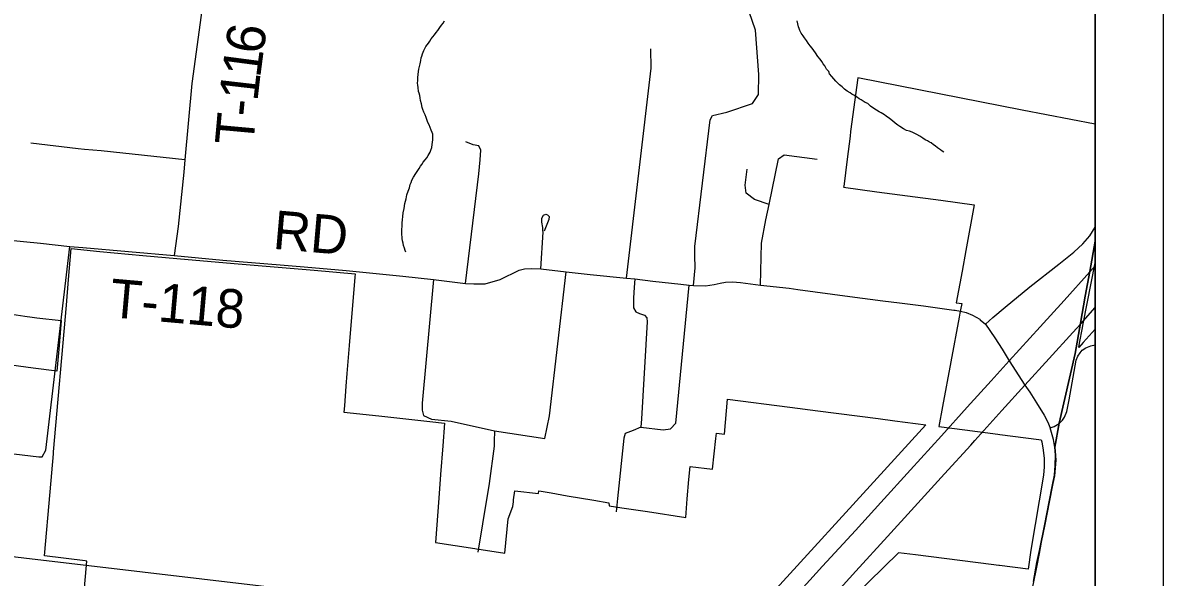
# Model space of a CAD drawing. Extents: x -7.3 to 34, y 0 to 22.
# Drawn here: x 7.321 to 9, y 18.898 to 19.714 of the extents above; entities that cross this region are included whole.
import ezdxf

# ---------------------------------------------------------------- set-up
doc = ezdxf.new("R2010")
doc.units = 0
for name, color, linetype in [('GM_X_Corporation', 7, 'Continuous'), ('GM_X_County_Road', 7, 'Continuous'), ('GM_X_Interstate_Route', 7, 'Continuous'), ('GM_X_Minor_River', 7, 'Continuous'), ('GM_X_Township_Road', 7, 'Continuous'), ('GM_X_Township_Road_Text', 7, 'Continuous'), ('SH_Data', 7, 'Continuous')]:
    doc.layers.add(name, color=color, linetype=linetype)

msp = doc.modelspace()

# ---------------------------------------------------------------- linework, layer by layer
at = {"layer": 'GM_X_Corporation'}
for points in [[(8.9, 14.1), (8.9, 19.7858), (8.8913, 19.7872), (7.8469, 19.8978), (7.6051, 19.9224), (6.9988, 19.9839), (6.9507, 19.9888), (6.4242, 20.0024), (6.4154, 20.0027), (6.0763, 20.0096), (6.0677, 20.0098), (6.0214, 20.0108), (5.9388, 20.0125), (5.8024, 20.0153), (4.9519, 20.0328), (4.9401, 20.0331), (4.9235, 20.0334), (4.7954, 20.036), (4.4762, 20.0428), (4.2328, 20.0479), (4.2288, 20.048), (2.7422, 20.0783)], [(8.8088, 18.8915), (8.8141, 18.9196), (8.8177, 18.9374), (8.8256, 18.9762), (8.8322, 19.0092), (8.8371, 19.0338), (8.8397, 19.0484), (8.841, 19.0624), (8.8412, 19.0775), (8.8403, 19.0896), (8.8467, 19.1247), (8.8704, 19.2273), (8.8782, 19.2717), (8.8852, 19.3116), (8.8919, 19.348), (8.9, 19.3924), (8.9, 19.7858)], [(8.9, 17.3436), (8.9, 19.2631), (8.8822, 19.2435), (8.8757, 19.2363), (8.8769, 19.2423), (8.8813, 19.2653), (8.8819, 19.2684), (8.8823, 19.2708), (8.8996, 19.3605), (8.9, 19.3625), (8.9, 19.5647), (8.7924, 19.5856), (8.5503, 19.6328), (8.5397, 19.5541), (8.5388, 19.5473), (8.5346, 19.5133), (8.5295, 19.4729), (8.5294, 19.4719), (8.5784, 19.4654), (8.6236, 19.4594), (8.6723, 19.4529), (8.7217, 19.4463), (8.7094, 19.3791), (8.7039, 19.3486), (8.6953, 19.3017), (8.6994, 19.3012), (8.7033, 19.3008), (8.7015, 19.2915), (8.7007, 19.2868), (8.6995, 19.2808), (8.6751, 19.1493), (8.6697, 19.12), (8.7078, 19.115), (8.7563, 19.1087), (8.7595, 19.1083), (8.8167, 19.1009), (8.8202, 19.1004), (8.8211, 19.0975), (8.8231, 19.085), (8.8245, 19.0727), (8.8247, 19.0604), (8.8236, 19.0481), (8.8053, 18.9378), (8.8012, 18.9097), (8.7588, 18.9151), (8.758, 18.9152), (8.7466, 18.9166), (8.6351, 18.9308), (8.6101, 18.934), (8.4786, 18.8052)], [(7.4105, 18.8711), (7.4151, 18.9217), (7.4122, 18.922), (7.3527, 18.9294), (7.3609, 19.0238), (7.3657, 19.0796), (7.366, 19.0825), (7.3848, 19.2985), (7.3881, 19.3362), (7.3917, 19.3816), (7.434, 19.3776), (7.4972, 19.3717), (7.5476, 19.367), (7.6316, 19.3598), (7.7495, 19.3497), (7.81, 19.3446), (7.8096, 19.3398), (7.8014, 19.2393), (7.798, 19.1979), (7.7965, 19.179), (7.7941, 19.1504), (7.7934, 19.141), (7.8447, 19.1354), (7.9024, 19.1291), (7.92, 19.1272), (7.9417, 19.1249), (7.9391, 19.0916), (7.9358, 19.0493), (7.9331, 19.0142), (7.9281, 18.949), (7.9864, 18.9401), (7.9911, 18.9394), (7.9958, 18.9387), (8.0305, 18.9334), (8.0355, 18.9841), (8.042, 19.0019), (8.043, 19.0089), (8.0433, 19.0117), (8.0451, 19.0253), (8.08, 19.0214), (8.0804, 19.0251), (8.0841, 19.0245), (8.0988, 19.022), (8.1223, 19.0179), (8.1615, 19.0112), (8.1835, 19.0077), (8.1842, 19.003), (8.1933, 19.0017), (8.2026, 19.0003), (8.2404, 18.9947), (8.2968, 18.9861), (8.2992, 19.0135), (8.3016, 19.0418), (8.3032, 19.0608), (8.3361, 19.057), (8.3414, 19.1021), (8.3418, 19.1059), (8.3423, 19.11), (8.3539, 19.1088), (8.3583, 19.1603), (8.4501, 19.1484), (8.4913, 19.1431), (8.5804, 19.1315), (8.6048, 19.1284), (8.6506, 19.1224), (8.3584, 18.8026)], [(8.9, 14.1), (8.9, 19.3924), (8.8919, 19.348), (8.8852, 19.3116), (8.8782, 19.2717), (8.8704, 19.2273), (8.8467, 19.1247), (8.8403, 19.0896), (8.8412, 19.0775), (8.841, 19.0624), (8.8397, 19.0484), (8.8371, 19.0338), (8.8322, 19.0092), (8.8256, 18.9762), (8.8177, 18.9374), (8.8141, 18.9196), (8.8088, 18.8915)], [(7.2979, 19.286), (7.3237, 19.2822), (7.3343, 19.2806), (7.3412, 19.2796), (7.3771, 19.2759), (7.3755, 19.2576), (7.3739, 19.2389), (7.3706, 19.2015), (7.336, 19.2059), (7.2812, 19.213)]]:
    msp.add_lwpolyline(points, dxfattribs=at)
msp.add_lwpolyline([(7.7589, 18.875), (7.6737, 17.8749), (6.6194, 17.9753), (6.71, 18.9987)], close=True, dxfattribs=at)
at = {"layer": 'GM_X_County_Road'}
msp.add_lwpolyline([(8.7923, 18.8076), (8.7989, 18.8415), (8.809, 18.8888), (8.8137, 18.9126), (8.8176, 18.9328), (8.8209, 18.9495), (8.8262, 18.9757), (8.8327, 19.0086), (8.8377, 19.0333), (8.8402, 19.0473), (8.8415, 19.0583), (8.8422, 19.0701), (8.8419, 19.077), (8.8406, 19.0891), (8.8386, 19.1005), (8.8337, 19.1181)], dxfattribs=at)
at = {"layer": 'GM_X_Interstate_Route'}
for points in [[(8.0485, 18.4186), (8.0571, 18.4281), (8.0916, 18.466), (8.1306, 18.5093), (8.1704, 18.5523), (8.2137, 18.6004), (8.2539, 18.6443), (8.2977, 18.6924), (8.3359, 18.735), (8.374, 18.7768), (8.4185, 18.8259), (8.4562, 18.8675), (8.4985, 18.9141), (8.5471, 18.967), (8.584, 19.0079), (8.6281, 19.0563), (8.6734, 19.1062), (8.7114, 19.1482), (8.7469, 19.1872), (8.7734, 19.2167), (8.8186, 19.2664), (8.8544, 19.3055), (8.8921, 19.3474), (8.9, 19.3561)], [(8.7165, 19.0926), (8.7226, 19.0992), (8.7623, 19.1433), (8.7964, 19.1809), (8.8321, 19.22), (8.8667, 19.2582), (8.8785, 19.2711), (8.9, 19.2949)], [(8.1035, 18.418), (8.1055, 18.4202), (8.1101, 18.4253), (8.1411, 18.4595), (8.181, 18.5035), (8.2198, 18.5461), (8.263, 18.5939), (8.3021, 18.6371), (8.3476, 18.6868), (8.3849, 18.728), (8.4244, 18.7711), (8.4683, 18.8193), (8.5057, 18.8606), (8.5476, 18.9069), (8.5941, 18.958), (8.6337, 19.0017), (8.678, 19.0504), (8.7165, 19.0926)]]:
    msp.add_lwpolyline(points, dxfattribs=at)
at = {"layer": 'GM_X_Minor_River'}
for points in [[(7.8845, 19.3764), (7.8838, 19.3791), (7.8827, 19.3825), (7.8813, 19.3863), (7.8806, 19.3898), (7.8799, 19.3932), (7.8792, 19.3963), (7.8793, 19.3989), (7.879, 19.402), (7.8787, 19.4058), (7.8788, 19.4099), (7.8793, 19.4149), (7.8794, 19.4194), (7.8798, 19.424), (7.8803, 19.4289), (7.8808, 19.4342), (7.8821, 19.4406), (7.8834, 19.4482), (7.8851, 19.455), (7.8863, 19.4607), (7.8883, 19.4664), (7.89, 19.4713), (7.8912, 19.4758), (7.8924, 19.4792), (7.8936, 19.4826), (7.896, 19.4867), (7.8992, 19.4923), (7.9023, 19.4968), (7.9042, 19.4998), (7.9062, 19.5028), (7.9082, 19.5054), (7.9101, 19.5088), (7.9129, 19.5122), (7.9156, 19.5152), (7.9176, 19.5185), (7.9191, 19.5212), (7.9203, 19.5238), (7.9215, 19.5264), (7.9227, 19.5306), (7.9236, 19.5347), (7.924, 19.5382), (7.9245, 19.5419), (7.9242, 19.5461), (7.9243, 19.5499), (7.9232, 19.5526), (7.9222, 19.5561), (7.9207, 19.5599), (7.9189, 19.5637), (7.9171, 19.5672), (7.916, 19.5702), (7.9146, 19.5745), (7.9132, 19.5787), (7.9114, 19.5825), (7.9099, 19.5863), (7.9088, 19.5894), (7.9075, 19.5947), (7.9064, 19.5997), (7.9057, 19.6035), (7.9051, 19.607), (7.9044, 19.6104), (7.9033, 19.6131), (7.9027, 19.6188), (7.9024, 19.6222), (7.902, 19.6253), (7.9021, 19.6291), (7.9022, 19.6332), (7.9027, 19.6385), (7.904, 19.6457), (7.9057, 19.6537), (7.9066, 19.6586), (7.9074, 19.6624), (7.9082, 19.665), (7.9091, 19.6684), (7.9111, 19.6733), (7.9142, 19.6793), (7.9181, 19.6842), (7.9201, 19.6868), (7.922, 19.6902), (7.9244, 19.6935), (7.9267, 19.6965), (7.9291, 19.6999), (7.9318, 19.7029), (7.9349, 19.707), (7.9373, 19.7104), (7.9396, 19.7137), (7.9416, 19.7171)], [(8.677, 19.5237), (8.6744, 19.5253), (8.6718, 19.5269), (8.6677, 19.53), (8.6643, 19.5328), (8.6617, 19.5343), (8.6583, 19.5371), (8.6557, 19.5383), (8.6527, 19.5402), (8.6497, 19.5418), (8.646, 19.5442), (8.6415, 19.5473), (8.637, 19.5497), (8.6332, 19.5517), (8.6302, 19.5529), (8.6265, 19.5545), (8.6219, 19.5557), (8.6178, 19.5581), (8.6122, 19.5612), (8.6092, 19.5632), (8.6055, 19.5663), (8.6014, 19.5695), (8.5969, 19.573), (8.592, 19.5765), (8.5894, 19.5785), (8.5846, 19.5816), (8.5819, 19.5828), (8.5778, 19.5852), (8.5737, 19.5879), (8.5688, 19.5911), (8.5648, 19.595), (8.561, 19.5969), (8.5584, 19.5985), (8.5554, 19.6005), (8.5524, 19.6021), (8.5498, 19.604), (8.5472, 19.6056), (8.5442, 19.6076), (8.5416, 19.6091), (8.5389, 19.6107), (8.5348, 19.6135), (8.5307, 19.6162), (8.527, 19.6197), (8.5233, 19.6228), (8.5207, 19.6252), (8.5181, 19.6283), (8.5151, 19.6314), (8.5121, 19.6348), (8.5088, 19.6391), (8.5074, 19.6422), (8.5044, 19.6457), (8.5015, 19.6507), (8.4993, 19.6537), (8.4975, 19.6572), (8.4949, 19.6603), (8.4915, 19.6642), (8.4879, 19.6699), (8.4831, 19.6765), (8.4801, 19.68), (8.4772, 19.6839), (8.4746, 19.6877), (8.472, 19.6919), (8.4698, 19.695), (8.4669, 19.6989), (8.4651, 19.7027), (8.464, 19.7054), (8.4629, 19.7081), (8.4619, 19.7123), (8.4608, 19.7169)]]:
    msp.add_lwpolyline(points, dxfattribs=at)
at = {"layer": 'GM_X_Township_Road'}
for p, q in [((8.7306, 19.2769), (8.7381, 19.2706)), ((8.1965, 19.0137), (8.1946, 18.9943)), ((7.9976, 18.9765), (7.9906, 18.9348))]:
    msp.add_line(p, q, dxfattribs=at)
for points in [[(7.6053, 19.9219), (7.5861, 19.7466), (7.5695, 19.6248), (7.5594, 19.5121), (7.5576, 19.494), (7.5493, 19.4144), (7.5434, 19.3715)], [(8.3085, 19.3272), (8.3108, 19.3535), (8.3105, 19.3714), (8.3105, 19.385), (8.3326, 19.571), (8.3362, 19.5774), (8.3575, 19.5826), (8.395, 19.5951), (8.404, 19.6085), (8.4044, 19.6378), (8.3994, 19.7032), (8.3902, 19.73), (8.3728, 19.7638), (8.3414, 19.8181)], [(8.2095, 19.3383), (8.246, 19.6474), (8.2455, 19.6755)], [(7.4112, 19.5277), (7.4023, 19.5285), (7.3323, 19.5368)], [(7.9727, 19.3305), (7.9923, 19.4919), (7.9942, 19.5121), (7.995, 19.5264), (7.9923, 19.5329), (7.9839, 19.5343), (7.973, 19.539)], [(7.5594, 19.5121), (7.4358, 19.5256), (7.4112, 19.5277)], [(8.4071, 19.3281), (8.4084, 19.3896), (8.4149, 19.424), (8.4196, 19.4468), (8.4333, 19.5137), (8.4418, 19.5199), (8.4902, 19.5131)], [(8.4196, 19.4468), (8.3981, 19.454), (8.3858, 19.4631), (8.3846, 19.4752), (8.3874, 19.4984)], [(8.0866, 19.4081), (8.0863, 19.4127), (8.0851, 19.4206), (8.0849, 19.4264), (8.0872, 19.4309), (8.0908, 19.4322), (8.0934, 19.4315), (8.0957, 19.4289), (8.0951, 19.4246), (8.0882, 19.4074)], [(8.0835, 19.352), (8.0868, 19.4058), (8.0866, 19.4081)], [(8.7381, 19.2706), (8.7493, 19.2805), (8.7672, 19.2956), (8.8038, 19.3254), (8.8461, 19.3587), (8.8682, 19.3766), (8.8815, 19.3889), (8.8918, 19.4007), (8.9, 19.413)], [(7.2031, 18.6729), (7.213, 18.7865), (7.2223, 18.8928), (7.2388, 18.9984), (7.2548, 19.0809), (7.258, 19.0854), (7.3442, 19.0751), (7.3492, 19.0753), (7.3547, 19.0851), (7.3897, 19.3848)], [(7.2968, 19.3946), (7.3465, 19.3896), (7.3897, 19.3848), (7.4089, 19.3832)], [(7.4089, 19.3832), (7.5434, 19.3715), (7.6151, 19.3647), (7.6994, 19.3576), (7.7349, 19.3549), (7.7966, 19.3495), (7.8801, 19.3413), (7.9256, 19.336), (7.9727, 19.3305), (7.9849, 19.3299), (8.0014, 19.3296), (8.0237, 19.3362), (8.0516, 19.3497), (8.0595, 19.352), (8.0696, 19.3522), (8.0835, 19.352), (8.121, 19.3477), (8.156, 19.3438), (8.2095, 19.3383), (8.2221, 19.337), (8.2482, 19.3337), (8.2897, 19.3294), (8.3021, 19.3277), (8.3085, 19.3272), (8.3258, 19.3267), (8.3389, 19.329), (8.3475, 19.3307), (8.3555, 19.3322), (8.3658, 19.3328), (8.3777, 19.332), (8.4071, 19.3281), (8.4491, 19.3232), (8.4617, 19.3213), (8.5383, 19.311), (8.5872, 19.3047), (8.6118, 19.3018), (8.6469, 19.2975), (8.6918, 19.2913), (8.6938, 19.2909)], [(8.0894, 19.1024), (8.096, 19.1354), (8.121, 19.3477)], [(7.9256, 19.336), (7.9088, 19.1543), (7.9086, 19.1437), (7.9109, 19.1361), (7.9223, 19.1306), (7.9516, 19.1277), (8.0154, 19.1136), (8.0894, 19.1024)], [(8.2221, 19.337), (8.221, 19.3245), (8.22, 19.3091), (8.22, 19.2945), (8.2235, 19.2885), (8.2287, 19.286), (8.2363, 19.2837), (8.2394, 19.2799), (8.2402, 19.2741), (8.2316, 19.1311), (8.2305, 19.1189), (8.2194, 19.1139), (8.2079, 19.1096), (8.2055, 19.1028), (8.1965, 19.0137)], [(8.2305, 19.1189), (8.2638, 19.1151), (8.2745, 19.1164), (8.2823, 19.125), (8.3021, 19.3277)], [(8.6938, 19.2909), (8.7017, 19.2896), (8.7098, 19.2874), (8.7193, 19.2835), (8.7298, 19.2776), (8.7306, 19.2769)], [(8.7381, 19.2706), (8.7519, 19.2505), (8.7628, 19.2338), (8.7734, 19.2167), (8.7964, 19.1809), (8.8037, 19.1702), (8.8135, 19.1547), (8.8245, 19.1365), (8.8294, 19.1274), (8.8337, 19.1181)], [(8.8337, 19.1181), (8.8395, 19.1199), (8.8469, 19.1242), (8.8518, 19.1292), (8.8548, 19.1338), (8.8579, 19.1417), (8.8614, 19.1592), (8.8719, 19.2176), (8.8743, 19.2236), (8.8775, 19.2285), (8.8809, 19.2322), (8.8861, 19.2358), (8.8936, 19.2386), (8.9, 19.2399)], [(8.0154, 19.1136), (8.0149, 19.0976), (8.0149, 19.0908), (8.0075, 19.036), (7.9976, 18.9765)]]:
    msp.add_lwpolyline(points, dxfattribs=at)
at = {"layer": 'SH_Data'}
for p, q in [((9, 21), (9, 14)), ((8.9, 20.9), (8.9, 14.1))]:
    msp.add_line(p, q, dxfattribs=at)

# ---------------------------------------------------------------- texts
at = {"layer": 'GM_X_Township_Road_Text'}
for s, height, rotation, p in [('6', 0.0568, 82.1172, (7.6745, 19.6664)), ('1', 0.0568, 82.547, (7.67, 19.6318)), ('1', 0.0568, 83.4546, (7.666, 19.5973)), ('-', 0.0568, 84.2847, (7.6637, 19.5743)), ('T', 0.0568, 84.8285, (7.6599, 19.5321)), ('RD', 0.05682, 355.0303, (7.6877, 19.3815)), ('T-118', 0.05682, 354.96, (7.4471, 19.281))]:
    msp.add_text(s, height=height, rotation=rotation, dxfattribs=at).set_placement(p)

doc.saveas('drawing.dxf')
